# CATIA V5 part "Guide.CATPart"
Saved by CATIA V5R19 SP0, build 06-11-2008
Part number: Guide
Bounding box of the stored display mesh (mm): x -5 to 5, y -5 to 5, z -25 to 25
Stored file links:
  D:\Shriniwas\v5_r19\c16_CAT_v5r19\c16_Part\Cam_Follower_msm_trial\Guide.CATPart
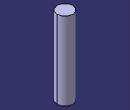
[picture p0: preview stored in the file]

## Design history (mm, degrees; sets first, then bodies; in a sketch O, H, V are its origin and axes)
Body1 (main body)
  Sketch1 on xy-plane, origin (0, 0, 0), H (1, 0, 0), V (0, 1, 0)
    circle A1 centre (0, 0) radius 5
    radius A1 = 5
  Pad1: profile Sketch1, direction (0, 0, 1), length 25, mirrored extent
